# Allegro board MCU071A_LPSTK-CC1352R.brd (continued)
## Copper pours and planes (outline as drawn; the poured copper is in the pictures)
GND on TOP: 1.52,0.27 1.45,0.28 1.38,0.29 30.52,0.29 30.52,8.37 0.57,8.37 0.57,40.16 0.86,40.82 1.52,41.11 51.97,41.11 52.63,40.82 52.93,40.16 52.93,11.21 52.92,14.68 51.92,13.13 51.72,11.3 51.67,11.32 51.67,11.3 51.72,11.29 52.12,10 52.92,8.91 52.92,11.19 52.93,1.22 52.63,0.56 51.97,0.27 ; 11 cut-outs
GND on BOTTOM: 30.51,0.26 30.51,8.36 0.55,8.36 0.55,8.79 1.79,11.68 0.55,14.56 0.55,40.46 0.8,40.86 1.21,41.1 52.25,41.1 52.66,40.87 52.91,40.47 52.91,0.87 52.68,0.5 52.31,0.26 38.57,0.26 38.57,1.67 31.37,1.67 31.37,0.26 ; 4 cut-outs
GND on L2: 1.5,0.26 1.42,0.27 1.34,0.28 30.51,0.28 30.52,8.36 0.58,8.35 0.58,1.01 0.56,1.11 0.55,1.21 0.55,8.8 1.78,11.69 0.55,14.58 0.55,40.14 0.84,40.81 1.5,41.1 51.96,41.1 52.62,40.81 52.91,40.14 52.91,1.21 52.62,0.55 51.96,0.26 ; 3 cut-outs
GND on L3: 30.52,0.26 30.52,8.36 0.56,8.35 0.56,1.13 0.55,1.21 0.55,8.79 1.78,11.67 0.55,14.55 0.55,40.14 0.84,40.81 1.5,41.1 51.96,41.1 52.62,40.81 52.91,40.14 52.91,14.69 51.68,11.79 52.91,8.9 52.91,1.21 52.62,0.55 51.96,0.26 38.57,0.26 38.57,1.67 31.37,1.67 31.37,0.26 ; 6 cut-outs
Net_36 on TOP (solid shape): 16.76,6.42 17.28,5.66 20.41,5.66 20.41,4.45 19.41,4.45 19.41,3.65 25.21,3.65 25.21,6.32 17.21,6.32 17.21,8.35 18.21,8.35 18.21,7.61 19.41,7.61 19.41,8.35 20.41,8.35 20.41,7.61 27.39,7.61 27.39,1.44 1.81,1.44 1.81,2.65 18.21,2.65 18.21,4.45 17.21,4.45 17.21,4.95 16.3,6.27 16.3,8.35 16.76,8.35
N3033151 on TOP: 34.25,5.82 35.7,5.82 35.12,7.79 34.83,7.79

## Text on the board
Ref Des/Silkscreen Bottom: LPRST | TCK | TMS | BPRST | TDI | TDO | 11 | 3 | 19 | 20 | 7 | 26 | 25 | 14 | 15 | 8 | 9 | 40 | 18 | 30 | 29 | 28 | 27 | 21 | 1 | 5 | 4 | 22 | 13 | 12 | 23 | 10 | 24 | 6 | GND | VDD BATT | VDD
User.Comments: MCU071 | REV A | CLASS 2 AND WORKMANSHIP SHALL CONFORM TO IPC-A-600, CLASS 2. CURRENT REVISIONS. | 5. ALL VIAS ARE TENTED. | 4. APPLY NON-CONDUCTIVE LPI SILKSCREEN OR EQUIVALENT PER THE ARTWORK.COLOR: WHITE. | 6. MAX. WARP & TWIST TO BE .0075 PER INCH. | 9. MANUFCTURER MARKING: TWO LETTER + YEAR +  WEEK | 3. SOLDERMASK ARTWORK HAS ZERO (0) OVERSIZED PADS.FABRICATION VENDOR IS ALLOWED TO ADJUST THE COMPONENT SOLDERMASK PADS TO MEET THEIR TOOLING REQUIREMENTS. | 7. BOARD MUST BE ELECTRICALLY TESTED USING SUPPLIED IPC-D-356 NETLIST. | 5. OVERALL BOARD THICKNESS TO BE 1.596 +/- 10%.AND APPLIES AFTER ALL LAMINATION AND PLATING | 4. BOARD MATERIAL & CONSTRUCTION TO BE U.L.94V-0 APPROVED AND MARKED ON THE FINISHED BOARD. | 8. 0.29 MM TRACES ON LAYER 1 ARE 50 OHMS +/-10%. THEY ARE REFERENCE TO LAYER 2 GROUND. | 3. BOARD MATERIAL SHALL BE 150 Tg/340 Td ISOLA | 2. THE PWB SHALL BE FABRICATED TO IPC-6012, | PROCESSES, MEASURED FROM COPPER TO COPPER. | PROCESS NOTES: | 2. PLATE ALL EXPOSED AREAS WITH ELECTROLESS NICKEL IMMERSION GOLD.NICKEL:100 MICRO-INCHES MIN. GOLD:2-8 MICROINCHES MIN. | LEAD FREE ASSEMBLY CAPABLE. BOARD MATERIAL SHALL MEET OR EXCEED IPC-4101B. | 1. ALL DIMENSIONS ARE IN MM, UNLESS | FAB NOTES: | 1. APPLY LPI SOLDERMASK OVER BARE COPPER (SMOBC),SOLDERMASK SHALL CONFORM TO IPC-SM-840. CLASS H. | CURRENT REV. COLOR OF MASK TO BE RED. | THE MARKING SHALL BE IN BOTTONM SILK SCREEN PRINT. | THE LETTER CODE SHALL IDENTIFY THE MANUFACTURER AND IS DECIDED BY  THE MFR. NO LOGOS OR OTHER IDENTIFIERS ARE ALLOWED | UL GUIDE NUMBER SHOULD BE MARKED ON THE FINISHED BOARD. | RoHS CERTIFICATE OF CONFORMANCE SHALL BE DELIVERED WITH EACH LOT. | OTHERWISE NOTED. | FR-4 OR EQUIVALENT, RoHS COMPLIANT AND | E2   Updated with IPC                                    2019-05-22  2019-05-22 | E1   Initial Version                                     2018-11-12  2018-11-12 | A    Production Release Version                          2019-09-04  2019-09-04
Ref Des/Silkscreen Top: LPRST | TX | RX | Coin | AAA | TDI | TMS | TDO | TCK | BPRST | NC | 30 | 28 | GND | X | Y | Z | 9 | 8 | 14 | 15 | 19 | 18 | 20 | Rev: A | MCU071 | 29 | 27 | 26 | 25 | 5 | 4 | 21 | 10 | 24 | 22 | 13 | 12 | 23 | 3 | 11 | 7 | 6 | VDD | PWR | BTN-2 | LEDs | 2.4GHz | Sub-1GHz | JTAG | OFF | ON | BTN-1 | LPSTK-CC1352R
XSECTION_CHART: *  SURFACE - AIR 0 MM | L1 TOP CONDUCTOR - COPPER 0.035 MM | *  DIELECTRIC - FR-4 0.175 MM | L2 L2 PLANE - COPPER 0.018 MM | *  DIELECTRIC - FR-4 1.14 MM | L3 L3 PLANE - COPPER 0.018 MM | L4 BOTTOM CONDUCTOR - COPPER 0.035 MM | DESIGN CROSS SECTION CHART | ___________________________ | TOTAL THICKNESS 1.596 MM
DIMENSION: Max R 0.40 (2 Plcs)
PAGE_OUTLINE: 2019-09-04 | X.XX : +/- 0.001 | SPECIFIED: | X : +/- 0.1 | X.X : +/- 0.01 | TOLERANCES UNLESS OTHERWISE | SVS, PM | FABRICATION DRAWING | LPSTK- CC1352R | MCU071  A | NONE | 1 OF 1
User.28: FIGURE | FINISHED_SIZE | 0.2 | 0.201 | 0.65 | 0.8 | 1.0 | 0.9 | 1.5x0.7 | DRILL CHART: TOP to BOTTOM | ALL UNITS ARE IN MILLIMETERS | PLATED | NON-PLATED | QTY | 525 | 25 | 5 | 3 | 40 | 4 | 2
